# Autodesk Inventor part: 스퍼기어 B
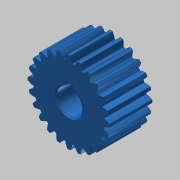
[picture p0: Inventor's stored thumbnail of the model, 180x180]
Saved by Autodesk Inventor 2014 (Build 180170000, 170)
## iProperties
Created: 2020-04
Part Number: 스퍼기어 B
Material: Steel
Document SubType Name: Modeling
Designer: mduedu
Categories: <?xml version="1.0" encoding="UTF-16"?> <MemberInstance><Categories><FamilyTemplate><FamilyTemplateParameter ValueType="xs:double" Id="1" ObjectReferenceKey="da
Density: 7.85 g/cm^3
Mass: 140.141 g
Surface Area: 65.0479 cm^2
Volume: 17.8524 cm^3
Appearance: 청록색
CustomPartVersion: 1
Author: mduedu
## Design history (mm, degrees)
sketch "Sketch1"
  geometry: C1 r 19.2 at (0, 0)
  constraints: 1 centre point
  dimensions: "d0" = 38.4 diameter of C1 (= da_da)
extrude "Extrusion1" new body sketch "Sketch1" distance "d1" = 20 (= da_b); taper "d2" = 0 deg
workplane "Work Plane2"
sketch "Sketch2"
  geometry: C1 r 19.2 at (0, 0) reference; C2 r 18 at (0, 0)
  constraints: 1 centre point, 1 coincident
  dimensions: "d3" = 36 diameter of C2 (= da_dw)
feature "피치 지름" sketch "Sketch2" dims "d4" = 10, "d5" = 0
workplane "Work Plane8"
workplane "Work Plane9"
feature "스퍼 기어" dims "da_b" = 20, "da_d" = 36, "da_aw" = 45, "da_da" = 38.4, "da_df" = 33.129, "da_dw" = 36, angle "da_beta" = 0 deg, "da_lefttooth" = 0, "da_righttooth" = 0
sketch "스케치3"
  geometry: L1 (-2, 5.657)-(2, 5.657); L2 (2, 5.657)-(2, 7.8); L3 (2, 7.8)-(-2, 7.8); L4 (-2, 7.8)-(-2, 5.657); A1 r 6 centre (0, 0) between (-2, 5.657) and (2, 5.657); 1 further point
  constraints: 8 end point, 2 parallel, 2 point on circle, 1 centre point, 1 coincident, 1 horizontal, 1 perpendicular
  dimensions: "d49" = 12 diameter of A1; "d51" = 4 distance of L2.end L3.end; "d52" = 13.8 dimension on A1 L3
extrude "돌출2" cut sketch "스케치3" stored distance "d53" = 10; taper "d54" = 0 deg
chamfer "모따기1" distance "d55" = 0.5; stored, may be unused: second distance "d56" = 2, angle "d57" = 45 deg
body "Solid1"
body "Srf1"
other parameters: "d16" = 45 (= da_aw), "d17" = 0, "d34" = 7.5 deg (computed from da_z), "d39" = 0, "d41" = 0, "d43" = 45 (= da_aw), "d46" = 45 (= da_aw), "d47" = 0, "d48" = 0
